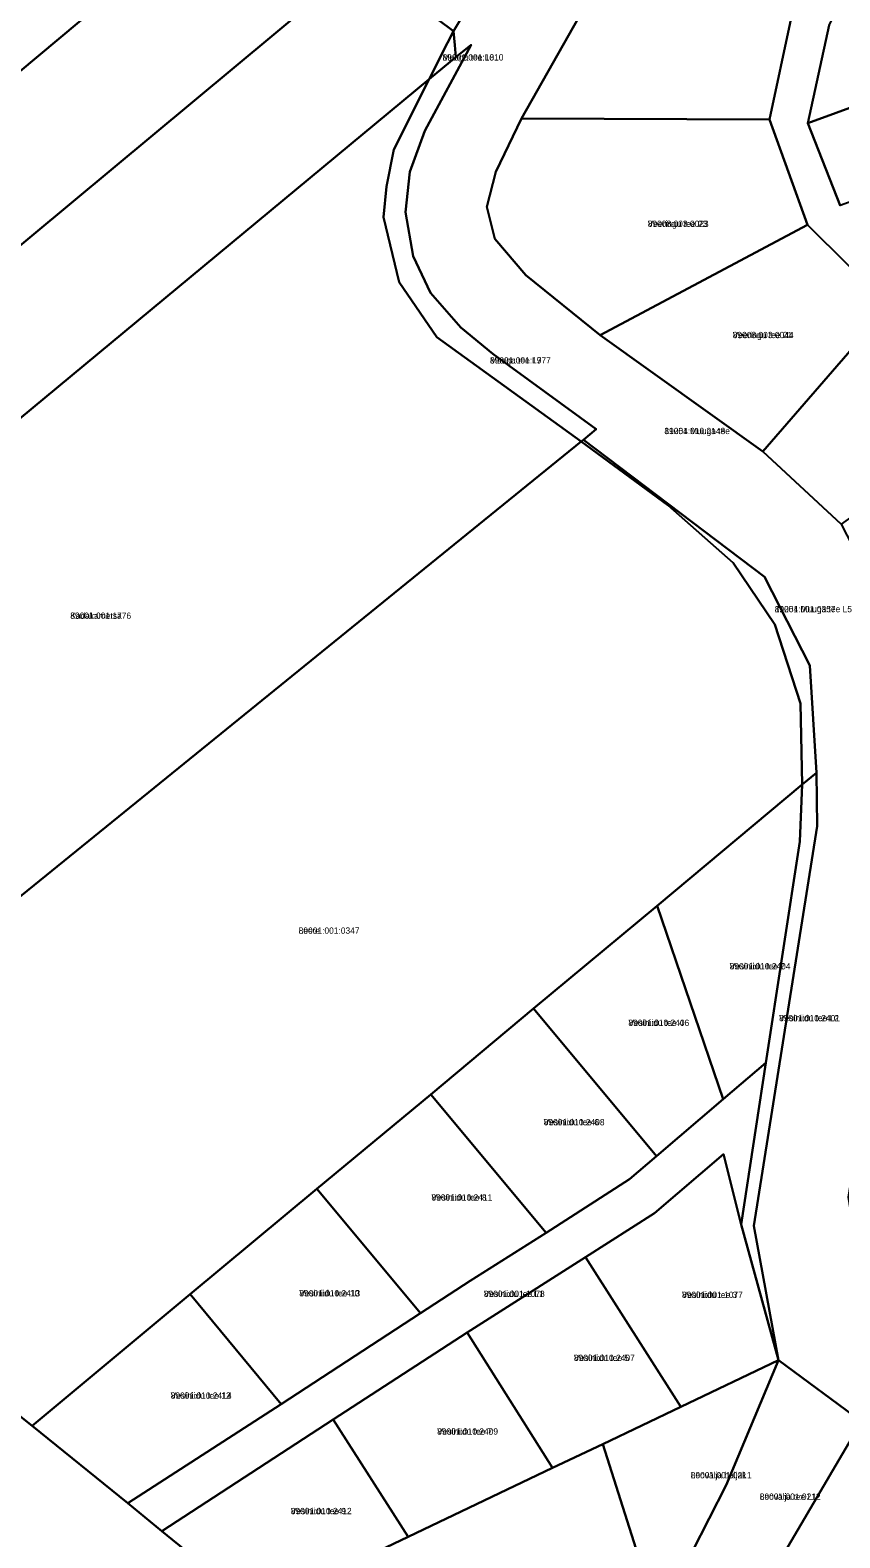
# Model space of a CAD drawing. Extents: x 526849 to 562296, y 6591741 to 6618546.
# Drawn here: x 551588.3 to 551781.3, y 6595150.6 to 6595510 of the extents above; entities that cross this region are included whole.
import ezdxf

# ---------------------------------------------------------------- set-up
doc = ezdxf.new("R2010")
doc.units = 0
for name, color, linetype in [('L_AADRESS', 7, 'Continuous'), ('PIIR', 7, 'Continuous'), ('TUNNUS', 7, 'Continuous')]:
    doc.layers.add(name, color=color, linetype=linetype)

msp = doc.modelspace()

# ---------------------------------------------------------------- linework, layer by layer
at = {"layer": 'PIIR'}
for points in [[(551689.2, 6595509.73), (551689.19, 6595509.72), (551667.09, 6595526.31), (551641.15, 6595546.5), (551640.61, 6595546.93), (551642.31, 6595548.28), (551669.5, 6595569.86), (551704.15, 6595536.14), (551690.58, 6595512.17)], [(551615.21, 6595566.32), (551639.82, 6595547.55), (551640.61, 6595546.93), (551641.15, 6595546.5), (551639.21, 6595544.88), (551390.09, 6595336.53), (551363.96, 6595357.62), (551613, 6595564.4)], [(551390.09, 6595336.53), (551639.21, 6595544.88), (551641.15, 6595546.5), (551667.09, 6595526.31), (551665.76, 6595525.2), (551415.09, 6595316.57)], [(551778.73, 6595511.21), (551791.57, 6595536.56), (551808.31, 6595500.49), (551773.6, 6595487.85)], [(551769.69, 6595512.86), (551764.49, 6595488.68), (551705.36, 6595488.91), (551730.21, 6595532.77)], [(551440.09, 6595296.62), (551415.09, 6595316.57), (551665.76, 6595525.2), (551667.09, 6595526.31), (551689.19, 6595509.72), (551687.78, 6595506.96), (551683.4, 6595498.31)], [(551674.98, 6595481.58), (551683.4, 6595498.31), (551689.77, 6595503.54), (551693.43, 6595506.53), (551682.38, 6595485.97), (551678.8, 6595476.2), (551677.75, 6595466.61), (551679.54, 6595456.09), (551683.69, 6595447.4), (551690.96, 6595439.09), (551698.57, 6595432.83), (551723.22, 6595414.85), (551720.14, 6595412.32), (551719.6, 6595411.91), (551685.23, 6595436.84), (551676.2, 6595449.94), (551672.53, 6595465.39), (551673.25, 6595472.69)], [(551689.77, 6595503.54), (551683.4, 6595498.31), (551687.78, 6595506.96), (551689.19, 6595509.72), (551689.49, 6595506.4)], [(551817.17, 6595481.15), (551781.34, 6595468.23), (551773.6, 6595487.85), (551808.31, 6595500.49)], [(551508.87, 6595241.01), (551440.09, 6595296.62), (551683.4, 6595498.31), (551674.98, 6595481.58), (551673.25, 6595472.69), (551672.53, 6595465.39), (551676.2, 6595449.94), (551685.23, 6595436.84), (551719.6, 6595411.91)], [(551773.57, 6595463.59), (551724.17, 6595437.26), (551706.41, 6595451.62), (551699.07, 6595460.23), (551697.13, 6595467.91), (551699.24, 6595476.2), (551705.36, 6595488.91), (551764.49, 6595488.68)], [(551793.02, 6595444.26), (551762.89, 6595409.54), (551724.17, 6595437.26), (551773.57, 6595463.59)], [(551245.73, 6595452.49), (551288.1, 6595418.83), (551338.19, 6595378.45), (551363.96, 6595357.62), (551390.09, 6595336.53), (551415.09, 6595316.57), (551440.09, 6595296.62), (551508.87, 6595241.01), (551588.75, 6595177.25), (551611.56, 6595158.81), (551619.69, 6595152.16), (551642.44, 6595133.65), (551611.3, 6595118.44), (551607.99, 6595116.82), (551588.73, 6595108.18), (551552.21, 6595089.9), (551528.52, 6595079.13), (551526.05, 6595081.12), (551174.82, 6595364.8)], [(551812.86, 6595428.2), (551818.81, 6595418.75), (551781.6, 6595392.24), (551762.89, 6595409.54), (551793.02, 6595444.26)], [(551588.75, 6595177.25), (551508.87, 6595241.01), (551719.6, 6595411.91), (551740.31, 6595396.74), (551755.85, 6595383.03), (551765.79, 6595368.33), (551771.87, 6595349.5), (551772.32, 6595330.13), (551737.7, 6595301.27), (551708.25, 6595276.75), (551683.78, 6595256.28), (551656.6, 6595233.79), (551626.44, 6595208.65)], [(551740.31, 6595396.74), (551719.6, 6595411.91), (551720.14, 6595412.32), (551763.35, 6595379.7), (551774.13, 6595358.55), (551775.68, 6595332.98), (551772.32, 6595330.13), (551771.87, 6595349.5), (551765.79, 6595368.33), (551755.85, 6595383.03)], [(551772.32, 6595330.13), (551775.68, 6595332.98), (551775.84, 6595320.2), (551760.74, 6595224.92), (551766.67, 6595192.89), (551757.74, 6595225.28), (551761.35, 6595248.71), (551763.63, 6595263.79), (551771.74, 6595316.55)], [(551737.7, 6595301.27), (551772.32, 6595330.13), (551771.74, 6595316.55), (551763.63, 6595263.79), (551753.49, 6595255.16)], [(551708.25, 6595276.75), (551737.7, 6595301.27), (551753.49, 6595255.16), (551737.6, 6595241.58)], [(551683.78, 6595256.28), (551708.25, 6595276.75), (551737.6, 6595241.58), (551731.14, 6595236.06), (551711.25, 6595223.32)], [(551619.69, 6595152.16), (551611.56, 6595158.81), (551648.1, 6595182.46), (551681.33, 6595204.15), (551693.15, 6595211.84), (551711.25, 6595223.32), (551731.14, 6595236.06), (551737.6, 6595241.58), (551753.49, 6595255.16), (551763.63, 6595263.79), (551761.35, 6595248.71), (551757.74, 6595225.28), (551753.5, 6595242), (551737.07, 6595227.96), (551720.62, 6595217.52), (551698.56, 6595203.45), (551692.42, 6595199.5), (551660.53, 6595178.76)], [(551656.6, 6595233.79), (551683.78, 6595256.28), (551711.25, 6595223.32), (551693.15, 6595211.84), (551681.33, 6595204.15)], [(551743.36, 6595181.78), (551720.62, 6595217.52), (551737.07, 6595227.96), (551753.5, 6595242), (551757.74, 6595225.28), (551766.67, 6595192.89)], [(551626.44, 6595208.65), (551656.6, 6595233.79), (551681.33, 6595204.15), (551648.1, 6595182.46)], [(551692.42, 6595199.5), (551698.56, 6595203.45), (551720.62, 6595217.52), (551743.36, 6595181.78), (551724.78, 6595172.88), (551712.77, 6595167.27)], [(551588.75, 6595177.25), (551626.44, 6595208.65), (551648.1, 6595182.46), (551611.56, 6595158.81)], [(551660.53, 6595178.76), (551692.42, 6595199.5), (551712.77, 6595167.27), (551678.35, 6595150.84)], [(551737.94, 6595131.37), (551724.78, 6595172.88), (551743.36, 6595181.78), (551766.67, 6595192.89), (551754.18, 6595163.11)], [(551754.18, 6595163.11), (551766.67, 6595192.89), (551786.42, 6595178.3), (551760.57, 6595134.35), (551745.14, 6595108.29), (551737.94, 6595131.37)], [(551642.44, 6595133.65), (551619.69, 6595152.16), (551660.53, 6595178.76), (551678.35, 6595150.84), (551647.12, 6595135.88)], [(551760.57, 6595134.35), (551786.42, 6595178.3), (551788.17, 6595176.98), (551807.99, 6595112.7), (551813.62, 6595094.81), (551800.86, 6595090.74)], [(551718.1, 6595097.71), (551647.12, 6595135.88), (551678.35, 6595150.84), (551712.77, 6595167.27), (551724.78, 6595172.88), (551737.94, 6595131.37)]]:
    msp.add_lwpolyline(points, close=True, dxfattribs=at)
for points in [[(551730.21, 6595532.77), (551705.36, 6595488.91), (551699.24, 6595476.2), (551697.13, 6595467.91), (551699.07, 6595460.23), (551706.41, 6595451.62), (551724.17, 6595437.26), (551762.89, 6595409.54), (551781.6, 6595392.24), (551792.52, 6595370.94), (551797.18, 6595351), (551796.87, 6595346.63), (551796, 6595314.31), (551791.98, 6595285.98), (551784.94, 6595242.36), (551783.24, 6595231.82), (551785.87, 6595215.25), (551790.58, 6595206.67), (551804.18, 6595195.59), (551842.96, 6595171.34), (551874.09, 6595152.87), (551897.93, 6595139.26)], [(551786.42, 6595178.3), (551766.67, 6595192.89), (551760.74, 6595224.92), (551775.84, 6595320.2), (551775.68, 6595332.98), (551774.13, 6595358.55), (551763.35, 6595379.7), (551720.14, 6595412.32), (551723.22, 6595414.85), (551698.57, 6595432.83), (551690.96, 6595439.09), (551683.69, 6595447.4), (551679.54, 6595456.09), (551677.75, 6595466.61), (551678.8, 6595476.2), (551682.38, 6595485.97), (551693.43, 6595506.53), (551689.77, 6595503.54), (551689.49, 6595506.4), (551689.19, 6595509.72), (551689.2, 6595509.73), (551690.58, 6595512.17)], [(551793.02, 6595444.26), (551773.57, 6595463.59), (551764.49, 6595488.68), (551769.69, 6595512.86)], [(551778.73, 6595511.21), (551773.6, 6595487.85), (551781.34, 6595468.23)]]:
    msp.add_lwpolyline(points, dxfattribs=at)

# ---------------------------------------------------------------- texts
at = {"layer": 'L_AADRESS'}
for s, p in [('Muuga tee L8', (551686.59, 6595502.76)), ('Veeringu tee 23', (551735.49, 6595463.09)), ('Veeringu tee 21', (551755.74, 6595436.57)), ('Muuga tee L9', (551697.88, 6595430.53)), ('11254 Muuga tee', (551739.45, 6595413.69)), ('Kadakametsa', (551597.85, 6595369.66)), ('11254 Muuga tee L5', (551765.75, 6595371.23)), ('Leete', (551652.29, 6595294.58)), ('Vesiniidu tee 2', (551755.01, 6595286.08)), ('Vesiniidu tee 4', (551730.87, 6595272.61)), ('Vesiniidu tee L2', (551766.79, 6595273.72)), ('Vesiniidu tee 6', (551710.69, 6595248.91)), ('Vesiniidu tee 8', (551683.93, 6595230.97)), ('Vesiniidu tee 10', (551652.44, 6595208.12)), ('Vesiniidu tee L1', (551696.43, 6595207.98)), ('Vesiniidu tee 3', (551743.64, 6595207.75)), ('Vesiniidu tee 5', (551717.89, 6595192.72)), ('Vesiniidu tee 12', (551621.79, 6595183.73)), ('Vesiniidu tee 7', (551685.3, 6595175.17)), ('Loovälja haljak', (551745.73, 6595164.75)), ('Vesiniidu tee 9', (551650.41, 6595156.21)), ('Loovälja tee L1', (551762.18, 6595159.64))]:
    msp.add_text(s, height=1.5, dxfattribs=at).set_placement(p)
at = {"layer": 'TUNNUS'}
for s, p in [('89001:001:1010', (551686.59, 6595502.76)), ('89008:003:0023', (551735.49, 6595463.09)), ('89008:003:0044', (551755.74, 6595436.57)), ('89001:001:1777', (551697.88, 6595430.53)), ('89001:010:2148', (551739.45, 6595413.69)), ('89001:001:1776', (551597.85, 6595369.66)), ('89001:001:0357', (551765.75, 6595371.23)), ('89001:001:0347', (551652.29, 6595294.58)), ('89001:010:2404', (551755.01, 6595286.08)), ('89001:010:2406', (551730.87, 6595272.61)), ('89001:010:2401', (551766.79, 6595273.72)), ('89001:010:2408', (551710.69, 6595248.91)), ('89001:010:2411', (551683.93, 6595230.97)), ('89001:010:2413', (551652.44, 6595208.12)), ('89001:001:1078', (551696.43, 6595207.98)), ('89001:001:1077', (551743.64, 6595207.75)), ('89001:010:2407', (551717.89, 6595192.72)), ('89001:010:2414', (551621.79, 6595183.73)), ('89001:010:2409', (551685.3, 6595175.17)), ('89001:001:0211', (551745.73, 6595164.75)), ('89001:010:2412', (551650.41, 6595156.21)), ('89001:001:0212', (551762.18, 6595159.64))]:
    msp.add_text(s, height=1.5, dxfattribs=at).set_placement(p)

doc.saveas('drawing.dxf')
